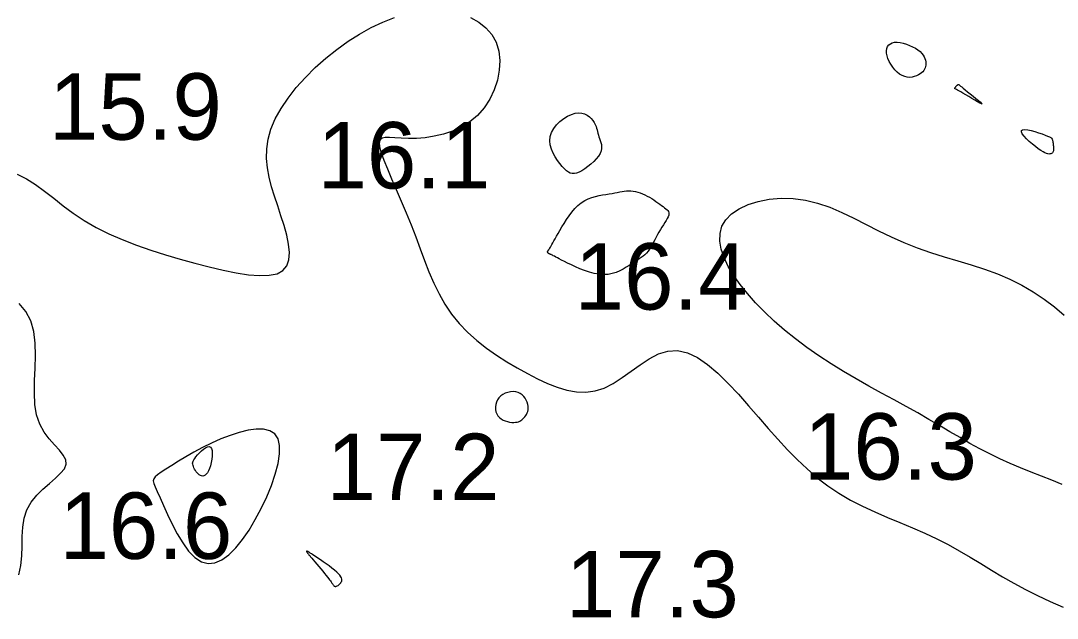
# Model space of a CAD drawing. Extents: x 3040093 to 3056816, y 408076 to 509144.
# Drawn here: x 3045282.9 to 3045360.9, y 434155.2 to 434200.2 of the extents above; entities that cross this region are included whole.
import ezdxf

# ---------------------------------------------------------------- set-up
doc = ezdxf.new("R2010")
doc.units = 0
doc.layers.add('V-CHAN-CONT-EL17', color=7, linetype='Continuous')
doc.layers.add('V-TOPO-SOUN-0610', color=7, linetype='Continuous')

msp = doc.modelspace()

# ---------------------------------------------------------------- linework, layer by layer
at = {"layer": 'V-CHAN-CONT-EL17'}
for points in [[(3045282.588, 434188.677), (3045283.296, 434188.33), (3045283.981, 434187.898), (3045284.659, 434187.401), (3045285.348, 434186.86), (3045286.064, 434186.296), (3045286.824, 434185.73), (3045287.645, 434185.181), (3045288.539, 434184.668), (3045289.499, 434184.192), (3045290.513, 434183.749), (3045291.569, 434183.339), (3045292.655, 434182.959), (3045293.758, 434182.606), (3045294.867, 434182.278), (3045295.969, 434181.974), (3045297.052, 434181.693), (3045298.099, 434181.445), (3045299.091, 434181.245), (3045300.011, 434181.106), (3045300.84, 434181.039), (3045301.562, 434181.06), (3045302.157, 434181.181), (3045302.607, 434181.414), (3045302.902, 434181.769), (3045303.056, 434182.233), (3045303.091, 434182.787), (3045303.026, 434183.413), (3045302.885, 434184.095), (3045302.688, 434184.814), (3045302.456, 434185.551), (3045302.21, 434186.291), (3045301.971, 434187.017), (3045301.754, 434187.732), (3045301.573, 434188.44), (3045301.442, 434189.147), (3045301.376, 434189.857), (3045301.388, 434190.576), (3045301.492, 434191.308), (3045301.702, 434192.059), (3045302.029, 434192.831), (3045302.464, 434193.617), (3045302.995, 434194.406), (3045303.609, 434195.19), (3045304.294, 434195.959), (3045305.038, 434196.702), (3045305.829, 434197.41), (3045306.653, 434198.072), (3045307.501, 434198.681), (3045308.365, 434199.23), (3045309.24, 434199.715), (3045310.122, 434200.131), (3045311.005, 434200.473)], [(3045316.714, 434200.474), (3045317.34, 434200.126), (3045317.879, 434199.696), (3045318.318, 434199.189), (3045318.643, 434198.604), (3045318.844, 434197.95), (3045318.924, 434197.242), (3045318.89, 434196.504), (3045318.748, 434195.756), (3045318.506, 434195.02), (3045318.171, 434194.318), (3045317.748, 434193.67), (3045317.245, 434193.099), (3045316.67, 434192.621), (3045316.039, 434192.233), (3045315.369, 434191.927), (3045314.677, 434191.695), (3045313.981, 434191.53), (3045313.299, 434191.424), (3045312.646, 434191.369), (3045312.042, 434191.356), (3045311.5, 434191.377), (3045311.027, 434191.412), (3045310.628, 434191.44), (3045310.305, 434191.44), (3045310.064, 434191.392), (3045309.909, 434191.273), (3045309.842, 434191.064), (3045309.869, 434190.743), (3045309.99, 434190.295), (3045310.193, 434189.731), (3045310.462, 434189.068), (3045310.782, 434188.323), (3045311.137, 434187.513), (3045311.511, 434186.655), (3045311.89, 434185.765), (3045312.257, 434184.861), (3045312.601, 434183.958), (3045312.93, 434183.062), (3045313.258, 434182.179), (3045313.595, 434181.313), (3045313.955, 434180.471), (3045314.351, 434179.658), (3045314.794, 434178.877), (3045315.298, 434178.135), (3045315.87, 434177.436), (3045316.505, 434176.779), (3045317.19, 434176.164), (3045317.915, 434175.588), (3045318.67, 434175.051), (3045319.443, 434174.551), (3045320.223, 434174.087), (3045321.001, 434173.659), (3045321.765, 434173.266), (3045322.517, 434172.92), (3045323.255, 434172.634), (3045323.982, 434172.422), (3045324.698, 434172.296), (3045325.403, 434172.27), (3045326.099, 434172.358), (3045326.787, 434172.573), (3045327.467, 434172.917), (3045328.143, 434173.356), (3045328.818, 434173.843), (3045329.495, 434174.333), (3045330.179, 434174.78), (3045330.872, 434175.138), (3045331.578, 434175.361), (3045332.3, 434175.405), (3045333.042, 434175.235), (3045333.798, 434174.871), (3045334.565, 434174.343), (3045335.338, 434173.685), (3045336.113, 434172.927), (3045336.884, 434172.101), (3045337.647, 434171.239), (3045338.398, 434170.372), (3045339.133, 434169.527), (3045339.859, 434168.712), (3045340.584, 434167.931), (3045341.314, 434167.187), (3045342.058, 434166.483), (3045342.823, 434165.824), (3045343.617, 434165.211), (3045344.448, 434164.65), (3045345.32, 434164.14), (3045346.226, 434163.674), (3045347.157, 434163.242), (3045348.101, 434162.834), (3045349.048, 434162.439), (3045349.989, 434162.047), (3045350.913, 434161.648), (3045351.809, 434161.232), (3045352.672, 434160.791), (3045353.507, 434160.328), (3045354.323, 434159.849), (3045355.133, 434159.36), (3045355.944, 434158.865), (3045356.767, 434158.371), (3045357.611, 434157.883), (3045358.488, 434157.406), (3045359.402, 434156.946), (3045360.351, 434156.504), (3045361.324, 434156.083)], [(3045361.255, 434165.316), (3045360.488, 434165.63), (3045359.706, 434165.939), (3045358.915, 434166.248), (3045358.123, 434166.564), (3045357.336, 434166.892), (3045356.561, 434167.239), (3045355.803, 434167.608), (3045355.056, 434167.999), (3045354.312, 434168.41), (3045353.565, 434168.84), (3045352.806, 434169.285), (3045352.028, 434169.744), (3045351.224, 434170.216), (3045350.385, 434170.697), (3045349.508, 434171.187), (3045348.597, 434171.687), (3045347.662, 434172.199), (3045346.712, 434172.725), (3045345.756, 434173.267), (3045344.802, 434173.827), (3045343.859, 434174.407), (3045342.936, 434175.009), (3045342.042, 434175.634), (3045341.182, 434176.279), (3045340.36, 434176.941), (3045339.583, 434177.616), (3045338.854, 434178.3), (3045338.179, 434178.991), (3045337.562, 434179.683), (3045337.01, 434180.375), (3045336.527, 434181.061), (3045336.122, 434181.737), (3045335.807, 434182.397), (3045335.592, 434183.034), (3045335.487, 434183.644), (3045335.502, 434184.22), (3045335.649, 434184.756), (3045335.936, 434185.248), (3045336.369, 434185.689), (3045336.934, 434186.071), (3045337.609, 434186.388), (3045338.375, 434186.631), (3045339.211, 434186.794), (3045340.096, 434186.87), (3045341.011, 434186.85), (3045341.935, 434186.728), (3045342.851, 434186.5), (3045343.76, 434186.182), (3045344.668, 434185.795), (3045345.578, 434185.358), (3045346.496, 434184.892), (3045347.427, 434184.417), (3045348.374, 434183.953), (3045349.344, 434183.521), (3045350.338, 434183.135), (3045351.35, 434182.787), (3045352.372, 434182.465), (3045353.394, 434182.154), (3045354.409, 434181.842), (3045355.407, 434181.516), (3045356.38, 434181.162), (3045357.319, 434180.767), (3045358.218, 434180.32), (3045359.075, 434179.822), (3045359.892, 434179.277), (3045360.669, 434178.688), (3045361.408, 434178.058)], [(3045282.727, 434158.519), (3045282.878, 434159.218), (3045282.947, 434159.941), (3045282.971, 434160.674), (3045282.986, 434161.401), (3045283.026, 434162.109), (3045283.129, 434162.784), (3045283.33, 434163.411), (3045283.652, 434163.981), (3045284.068, 434164.496), (3045284.538, 434164.963), (3045285.022, 434165.391), (3045285.479, 434165.785), (3045285.869, 434166.154), (3045286.153, 434166.503), (3045286.289, 434166.841), (3045286.252, 434167.176), (3045286.067, 434167.519), (3045285.773, 434167.886), (3045285.411, 434168.29), (3045285.019, 434168.744), (3045284.636, 434169.263), (3045284.303, 434169.86), (3045284.059, 434170.55), (3045283.93, 434171.339), (3045283.893, 434172.208), (3045283.914, 434173.131), (3045283.956, 434174.081), (3045283.984, 434175.032), (3045283.964, 434175.958), (3045283.859, 434176.833), (3045283.634, 434177.63), (3045283.263, 434178.329), (3045282.757, 434178.929)]]:
    msp.add_lwpolyline(points, dxfattribs=at)
for points in [[(3045348.845, 434198.612), (3045349.065, 434198.587), (3045349.297, 434198.537), (3045349.535, 434198.465), (3045349.771, 434198.374), (3045349.999, 434198.269), (3045350.21, 434198.152), (3045350.397, 434198.029), (3045350.556, 434197.901), (3045350.686, 434197.771), (3045350.79, 434197.639), (3045350.871, 434197.507), (3045350.93, 434197.377), (3045350.97, 434197.248), (3045350.993, 434197.123), (3045351.001, 434197.003), (3045350.997, 434196.888), (3045350.979, 434196.778), (3045350.948, 434196.673), (3045350.903, 434196.574), (3045350.841, 434196.479), (3045350.764, 434196.389), (3045350.67, 434196.303), (3045350.558, 434196.222), (3045350.429, 434196.145), (3045350.283, 434196.076), (3045350.124, 434196.02), (3045349.954, 434195.982), (3045349.775, 434195.966), (3045349.59, 434195.977), (3045349.401, 434196.019), (3045349.212, 434196.097), (3045349.023, 434196.213), (3045348.841, 434196.362), (3045348.667, 434196.539), (3045348.506, 434196.736), (3045348.363, 434196.947), (3045348.24, 434197.164), (3045348.143, 434197.382), (3045348.074, 434197.593), (3045348.038, 434197.792), (3045348.034, 434197.975), (3045348.061, 434198.14), (3045348.12, 434198.285), (3045348.208, 434198.406), (3045348.325, 434198.502), (3045348.471, 434198.57), (3045348.645, 434198.607)], [(3045353.177, 434195.145), (3045353.185, 434195.168), (3045353.199, 434195.193), (3045353.218, 434195.22), (3045353.239, 434195.247), (3045353.263, 434195.275), (3045353.288, 434195.302), (3045353.311, 434195.327), (3045353.333, 434195.35), (3045353.353, 434195.371), (3045353.372, 434195.389), (3045353.389, 434195.404), (3045353.405, 434195.416), (3045353.419, 434195.424), (3045353.433, 434195.429), (3045353.447, 434195.43), (3045353.461, 434195.427), (3045353.479, 434195.417), (3045353.507, 434195.396), (3045353.548, 434195.362), (3045353.609, 434195.312), (3045353.694, 434195.242), (3045353.808, 434195.148), (3045353.955, 434195.029), (3045354.137, 434194.883), (3045354.342, 434194.718), (3045354.556, 434194.546), (3045354.763, 434194.378), (3045354.948, 434194.224), (3045355.096, 434194.096), (3045355.192, 434194.004), (3045355.221, 434193.959), (3045355.173, 434193.969), (3045355.057, 434194.027), (3045354.889, 434194.121), (3045354.684, 434194.243), (3045354.457, 434194.38), (3045354.222, 434194.522), (3045353.995, 434194.658), (3045353.79, 434194.779), (3045353.62, 434194.875), (3045353.484, 434194.949), (3045353.378, 434195.004), (3045353.299, 434195.043), (3045353.242, 434195.071), (3045353.206, 434195.091), (3045353.185, 434195.108), (3045353.177, 434195.125)], [(3045322.82, 434191.816), (3045322.985, 434192.112), (3045323.2, 434192.389), (3045323.454, 434192.641), (3045323.733, 434192.861), (3045324.026, 434193.043), (3045324.319, 434193.18), (3045324.602, 434193.266), (3045324.862, 434193.296), (3045325.099, 434193.276), (3045325.312, 434193.215), (3045325.502, 434193.12), (3045325.67, 434192.999), (3045325.814, 434192.86), (3045325.935, 434192.712), (3045326.034, 434192.562), (3045326.112, 434192.418), (3045326.171, 434192.278), (3045326.216, 434192.144), (3045326.252, 434192.012), (3045326.282, 434191.881), (3045326.311, 434191.752), (3045326.343, 434191.622), (3045326.382, 434191.49), (3045326.431, 434191.356), (3045326.483, 434191.217), (3045326.532, 434191.073), (3045326.57, 434190.923), (3045326.591, 434190.765), (3045326.585, 434190.598), (3045326.547, 434190.422), (3045326.469, 434190.234), (3045326.346, 434190.036), (3045326.185, 434189.832), (3045325.993, 434189.628), (3045325.781, 434189.43), (3045325.556, 434189.245), (3045325.328, 434189.079), (3045325.105, 434188.938), (3045324.896, 434188.828), (3045324.708, 434188.755), (3045324.539, 434188.719), (3045324.382, 434188.719), (3045324.234, 434188.756), (3045324.09, 434188.829), (3045323.944, 434188.938), (3045323.791, 434189.082), (3045323.627, 434189.261), (3045323.45, 434189.473), (3045323.268, 434189.716), (3045323.093, 434189.982), (3045322.936, 434190.268), (3045322.809, 434190.569), (3045322.722, 434190.879), (3045322.688, 434191.194), (3045322.719, 434191.508)], [(3045359.24, 434190.751), (3045359.01, 434190.939), (3045358.782, 434191.141), (3045358.57, 434191.346), (3045358.39, 434191.542), (3045358.256, 434191.718), (3045358.184, 434191.864), (3045358.189, 434191.968), (3045358.279, 434192.024), (3045358.444, 434192.035), (3045358.664, 434192.01), (3045358.922, 434191.957), (3045359.2, 434191.884), (3045359.48, 434191.799), (3045359.744, 434191.71), (3045359.974, 434191.625), (3045360.156, 434191.55), (3045360.292, 434191.486), (3045360.391, 434191.428), (3045360.457, 434191.375), (3045360.499, 434191.324), (3045360.523, 434191.273), (3045360.536, 434191.219), (3045360.544, 434191.16), (3045360.554, 434191.093), (3045360.565, 434191.02), (3045360.576, 434190.943), (3045360.587, 434190.864), (3045360.597, 434190.784), (3045360.604, 434190.705), (3045360.608, 434190.628), (3045360.609, 434190.557), (3045360.604, 434190.491), (3045360.594, 434190.432), (3045360.578, 434190.379), (3045360.556, 434190.333), (3045360.526, 434190.293), (3045360.49, 434190.26), (3045360.446, 434190.233), (3045360.394, 434190.212), (3045360.333, 434190.199), (3045360.261, 434190.195), (3045360.175, 434190.205), (3045360.074, 434190.233), (3045359.954, 434190.281), (3045359.812, 434190.354), (3045359.648, 434190.454), (3045359.457, 434190.586)], [(3045322.608, 434182.693), (3045322.589, 434182.706), (3045322.571, 434182.721), (3045322.555, 434182.738), (3045322.541, 434182.757), (3045322.53, 434182.778), (3045322.524, 434182.8), (3045322.522, 434182.823), (3045322.527, 434182.848), (3045322.537, 434182.876), (3045322.554, 434182.907), (3045322.576, 434182.945), (3045322.605, 434182.991), (3045322.64, 434183.045), (3045322.682, 434183.111), (3045322.731, 434183.188), (3045322.786, 434183.28), (3045322.849, 434183.388), (3045322.922, 434183.512), (3045323.004, 434183.656), (3045323.098, 434183.819), (3045323.204, 434184.004), (3045323.323, 434184.211), (3045323.457, 434184.444), (3045323.606, 434184.701), (3045323.77, 434184.975), (3045323.95, 434185.259), (3045324.143, 434185.544), (3045324.351, 434185.821), (3045324.572, 434186.083), (3045324.807, 434186.321), (3045325.054, 434186.526), (3045325.314, 434186.693), (3045325.582, 434186.825), (3045325.854, 434186.927), (3045326.128, 434187.005), (3045326.398, 434187.064), (3045326.662, 434187.11), (3045326.915, 434187.149), (3045327.153, 434187.186), (3045327.374, 434187.225), (3045327.579, 434187.265), (3045327.771, 434187.305), (3045327.953, 434187.342), (3045328.127, 434187.374), (3045328.296, 434187.4), (3045328.463, 434187.416), (3045328.631, 434187.421), (3045328.801, 434187.413), (3045328.974, 434187.392), (3045329.149, 434187.36), (3045329.325, 434187.315), (3045329.501, 434187.26), (3045329.676, 434187.194), (3045329.851, 434187.118), (3045330.023, 434187.032), (3045330.193, 434186.939), (3045330.36, 434186.838), (3045330.521, 434186.734), (3045330.677, 434186.627), (3045330.825, 434186.521), (3045330.966, 434186.418), (3045331.098, 434186.32), (3045331.22, 434186.23), (3045331.33, 434186.148), (3045331.428, 434186.074), (3045331.511, 434186.002), (3045331.577, 434185.931), (3045331.625, 434185.857), (3045331.652, 434185.777), (3045331.658, 434185.687), (3045331.639, 434185.585), (3045331.596, 434185.467), (3045331.531, 434185.336), (3045331.448, 434185.191), (3045331.351, 434185.034), (3045331.244, 434184.868), (3045331.131, 434184.692), (3045331.017, 434184.509), (3045330.904, 434184.32), (3045330.797, 434184.127), (3045330.694, 434183.932), (3045330.594, 434183.737), (3045330.495, 434183.546), (3045330.396, 434183.361), (3045330.296, 434183.185), (3045330.191, 434183.021), (3045330.082, 434182.87), (3045329.967, 434182.736), (3045329.843, 434182.615), (3045329.711, 434182.503), (3045329.569, 434182.396), (3045329.416, 434182.291), (3045329.251, 434182.183), (3045329.073, 434182.07), (3045328.88, 434181.946), (3045328.672, 434181.81), (3045328.448, 434181.668), (3045328.208, 434181.527), (3045327.951, 434181.395), (3045327.676, 434181.28), (3045327.384, 434181.19), (3045327.073, 434181.131), (3045326.743, 434181.112), (3045326.396, 434181.138), (3045326.036, 434181.203), (3045325.672, 434181.3), (3045325.31, 434181.42), (3045324.958, 434181.556), (3045324.622, 434181.7), (3045324.311, 434181.843), (3045324.031, 434181.978), (3045323.788, 434182.098), (3045323.58, 434182.203), (3045323.404, 434182.294), (3045323.257, 434182.373), (3045323.134, 434182.438), (3045323.033, 434182.493), (3045322.95, 434182.538), (3045322.882, 434182.574), (3045322.826, 434182.602), (3045322.78, 434182.623), (3045322.743, 434182.639), (3045322.712, 434182.65), (3045322.687, 434182.659), (3045322.665, 434182.667), (3045322.646, 434182.674), (3045322.627, 434182.682)], [(3045320.103, 434169.993), (3045320.222, 434170.012), (3045320.329, 434170.042), (3045320.425, 434170.082), (3045320.513, 434170.132), (3045320.594, 434170.19), (3045320.669, 434170.257), (3045320.741, 434170.331), (3045320.811, 434170.411), (3045320.876, 434170.499), (3045320.935, 434170.594), (3045320.985, 434170.697), (3045321.025, 434170.808), (3045321.051, 434170.928), (3045321.063, 434171.058), (3045321.056, 434171.198), (3045321.03, 434171.347), (3045320.985, 434171.501), (3045320.92, 434171.655), (3045320.835, 434171.804), (3045320.731, 434171.943), (3045320.608, 434172.065), (3045320.465, 434172.167), (3045320.304, 434172.242), (3045320.124, 434172.287), (3045319.931, 434172.302), (3045319.731, 434172.288), (3045319.531, 434172.247), (3045319.337, 434172.181), (3045319.156, 434172.09), (3045318.992, 434171.976), (3045318.853, 434171.84), (3045318.744, 434171.685), (3045318.665, 434171.515), (3045318.616, 434171.336), (3045318.595, 434171.152), (3045318.603, 434170.97), (3045318.638, 434170.793), (3045318.699, 434170.629), (3045318.787, 434170.481), (3045318.9, 434170.354), (3045319.033, 434170.248), (3045319.181, 434170.162), (3045319.339, 434170.095), (3045319.502, 434170.044), (3045319.665, 434170.01), (3045319.823, 434169.991), (3045319.97, 434169.986)], [(3045296.967, 434159.352), (3045297.483, 434159.414), (3045298.005, 434159.645), (3045298.527, 434160.027), (3045299.046, 434160.539), (3045299.555, 434161.163), (3045300.049, 434161.878), (3045300.524, 434162.666), (3045300.972, 434163.506), (3045301.382, 434164.374), (3045301.738, 434165.244), (3045302.028, 434166.093), (3045302.237, 434166.893), (3045302.35, 434167.622), (3045302.355, 434168.252), (3045302.237, 434168.76), (3045301.988, 434169.127), (3045301.619, 434169.361), (3045301.15, 434169.474), (3045300.598, 434169.482), (3045299.982, 434169.398), (3045299.319, 434169.237), (3045298.627, 434169.013), (3045297.926, 434168.739), (3045297.23, 434168.429), (3045296.553, 434168.095), (3045295.904, 434167.748), (3045295.293, 434167.401), (3045294.731, 434167.064), (3045294.228, 434166.749), (3045293.793, 434166.467), (3045293.437, 434166.231), (3045293.168, 434166.045), (3045292.982, 434165.891), (3045292.876, 434165.747), (3045292.844, 434165.587), (3045292.88, 434165.387), (3045292.981, 434165.125), (3045293.14, 434164.776), (3045293.352, 434164.316), (3045293.613, 434163.732), (3045293.919, 434163.057), (3045294.265, 434162.333), (3045294.648, 434161.602), (3045295.063, 434160.909), (3045295.507, 434160.295), (3045295.974, 434159.804), (3045296.463, 434159.479)], [(3045296.179, 434167.544), (3045296.32, 434167.692), (3045296.473, 434167.837), (3045296.631, 434167.968), (3045296.786, 434168.075), (3045296.93, 434168.145), (3045297.057, 434168.169), (3045297.158, 434168.134), (3045297.228, 434168.034), (3045297.268, 434167.879), (3045297.282, 434167.681), (3045297.273, 434167.453), (3045297.244, 434167.21), (3045297.199, 434166.964), (3045297.14, 434166.729), (3045297.072, 434166.518), (3045296.997, 434166.342), (3045296.916, 434166.201), (3045296.831, 434166.093), (3045296.744, 434166.016), (3045296.654, 434165.969), (3045296.565, 434165.95), (3045296.476, 434165.955), (3045296.388, 434165.984), (3045296.304, 434166.034), (3045296.224, 434166.102), (3045296.148, 434166.183), (3045296.078, 434166.274), (3045296.014, 434166.372), (3045295.957, 434166.472), (3045295.907, 434166.571), (3045295.866, 434166.665), (3045295.834, 434166.751), (3045295.814, 434166.832), (3045295.807, 434166.912), (3045295.816, 434166.993), (3045295.843, 434167.079), (3045295.891, 434167.174), (3045295.962, 434167.281), (3045296.057, 434167.404)], [(3045304.462, 434160.143), (3045304.477, 434160.125), (3045304.497, 434160.101), (3045304.525, 434160.068), (3045304.564, 434160.022), (3045304.616, 434159.959), (3045304.686, 434159.877), (3045304.776, 434159.77), (3045304.887, 434159.637), (3045305.016, 434159.482), (3045305.158, 434159.312), (3045305.306, 434159.133), (3045305.456, 434158.952), (3045305.602, 434158.775), (3045305.738, 434158.608), (3045305.86, 434158.458), (3045305.963, 434158.329), (3045306.049, 434158.221), (3045306.119, 434158.131), (3045306.176, 434158.055), (3045306.222, 434157.991), (3045306.261, 434157.936), (3045306.293, 434157.888), (3045306.322, 434157.844), (3045306.349, 434157.802), (3045306.376, 434157.762), (3045306.404, 434157.725), (3045306.434, 434157.693), (3045306.466, 434157.668), (3045306.502, 434157.65), (3045306.542, 434157.641), (3045306.587, 434157.642), (3045306.639, 434157.655), (3045306.694, 434157.677), (3045306.752, 434157.709), (3045306.81, 434157.75), (3045306.865, 434157.797), (3045306.916, 434157.851), (3045306.961, 434157.911), (3045306.998, 434157.974), (3045307.024, 434158.041), (3045307.036, 434158.113), (3045307.032, 434158.191), (3045307.007, 434158.276), (3045306.96, 434158.371), (3045306.887, 434158.475), (3045306.785, 434158.592), (3045306.65, 434158.722), (3045306.482, 434158.865), (3045306.288, 434159.019), (3045306.077, 434159.178), (3045305.856, 434159.337), (3045305.636, 434159.491), (3045305.424, 434159.636), (3045305.23, 434159.768), (3045305.063, 434159.88), (3045304.929, 434159.969), (3045304.826, 434160.038), (3045304.75, 434160.09), (3045304.696, 434160.126), (3045304.66, 434160.15), (3045304.637, 434160.166), (3045304.623, 434160.175), (3045304.614, 434160.182), (3045304.605, 434160.188), (3045304.597, 434160.195), (3045304.588, 434160.202), (3045304.578, 434160.209), (3045304.566, 434160.216), (3045304.553, 434160.225), (3045304.538, 434160.234), (3045304.521, 434160.244), (3045304.501, 434160.255), (3045304.48, 434160.267), (3045304.458, 434160.278), (3045304.436, 434160.287), (3045304.417, 434160.295), (3045304.4, 434160.299), (3045304.386, 434160.3), (3045304.378, 434160.297), (3045304.375, 434160.288), (3045304.378, 434160.275), (3045304.384, 434160.259), (3045304.394, 434160.24), (3045304.406, 434160.22), (3045304.42, 434160.2), (3045304.434, 434160.179), (3045304.448, 434160.161)]]:
    msp.add_lwpolyline(points, close=True, dxfattribs=at)

# ---------------------------------------------------------------- texts
at = {"layer": 'V-TOPO-SOUN-0610'}
for s, p in [('15.9 ', (3045284.993, 434191.27)), ('16.1 ', (3045305.203, 434187.6)), ('16.4 ', (3045324.563, 434178.48)), ('16.3 ', (3045341.823, 434165.68)), ('17.2 ', (3045305.893, 434164.14)), ('16.6 ', (3045285.783, 434159.71)), ('17.3 ', (3045323.903, 434155.31))]:
    msp.add_text(s, height=5, dxfattribs=at).set_placement(p)

doc.saveas('drawing.dxf')
